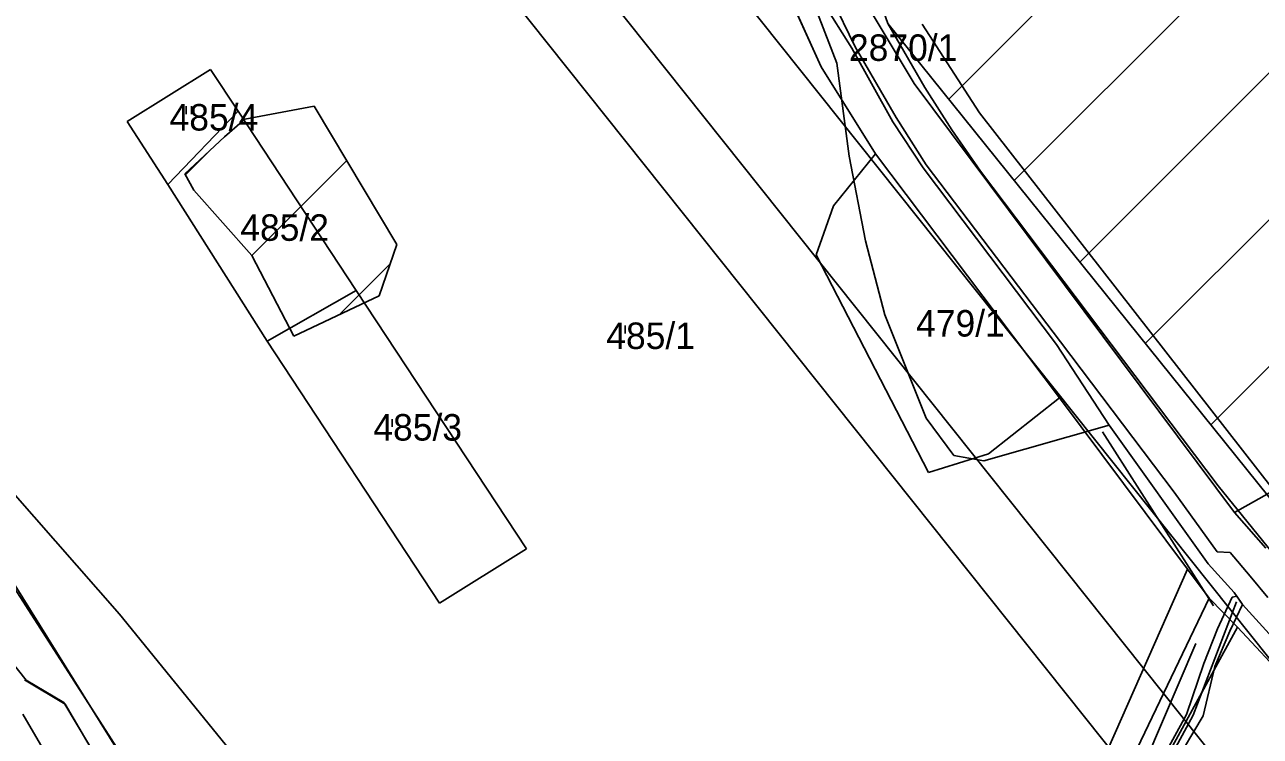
# Model space of a CAD drawing. Extents: x -564810 to -550519, y -1045831 to -1034011.
# Drawn here: x -554457.1 to -554219.2, y -1035858.3 to -1035721.3 of the extents above; entities that cross this region are included whole.
import ezdxf

# ---------------------------------------------------------------- set-up
doc = ezdxf.new("R2010")
doc.units = 0
for name, color, linetype in [('Biokoridory', 7, 'Continuous'), ('Interakční prvky', 7, 'Continuous'), ('KN stav', 7, 'Continuous'), ('Lesní porost', 7, 'Continuous'), ('Obvod KPU', 7, 'Continuous'), ('Odvodněné plochy', 7, 'Continuous'), ('Parcelní čísla', 7, 'Continuous'), ('Plynovod', 7, 'Continuous'), ('STG', 7, 'Continuous'), ('vodní toky', 7, 'Continuous'), ('Vrstva 33', 7, 'Continuous'), ('Vrstva 39', 7, 'Continuous'), ('Vrstva 4', 7, 'Continuous'), ('zamokř ploch', 7, 'Continuous')]:
    doc.layers.add(name, color=color, linetype=linetype)

msp = doc.modelspace()

# ---------------------------------------------------------------- linework, layer by layer
at = {"layer": 'Biokoridory'}
for points in [[(-554537.39, -1035746.04), (-554479.56, -1035788.42), (-554438.9, -1035834.8), (-554396.53, -1035886.91), (-554371.91, -1035929.28), (-554370.76, -1035993.98), (-554383.93, -1036106.79), (-554397.67, -1036162.33), (-554405.12, -1036209.86), (-554428.6, -1036243.51), (-554384.5, -1036328.39)], [(-554418.63, -1036320.62), (-554443.83, -1036285.12), (-554447.83, -1036247.33), (-554435.81, -1036214.69), (-554412.9, -1036187.21), (-554413.48, -1036143.11), (-554398.59, -1036095.59), (-554384.27, -1036003.97), (-554390.57, -1035936.4), (-554411.19, -1035894.6), (-554437.53, -1035863.68), (-554459.29, -1035828.75), (-554491.35, -1035800.69), (-554517.12, -1035776.07), (-554550.9, -1035757.75)]]:
    msp.add_lwpolyline(points, dxfattribs=at)
at = {"layer": 'Interakční prvky'}
msp.add_line((-554249.62, -1035799.65), (-554228.23, -1035833.15), dxfattribs=at)
msp.add_lwpolyline([(-554401.17, -1036035.23), (-554362.09, -1036026.51), (-554331.09, -1036007.77), (-554306.54, -1035979.02), (-554289.43, -1035956.72), (-554271.99, -1035924.74), (-554250.67, -1035885), (-554231.62, -1035840.41)], dxfattribs=at)
at = {"layer": 'KN stav'}
for p, q in [((-554312.36, -1035710.33), (-554303.79, -1035729.39)), ((-554303.79, -1035729.39), (-554312.36, -1035710.33)), ((-554296.78, -1035714.31), (-554285.86, -1035732.63)), ((-554421.35, -1035729.89), (-554437.42, -1035739.94)), ((-554437.42, -1035739.94), (-554421.35, -1035729.89)), ((-554416.04, -1035737.96), (-554421.35, -1035729.89)), ((-554421.35, -1035729.89), (-554416.04, -1035737.96)), ((-554303.79, -1035729.39), (-554293.31, -1035746.12)), ((-554293.31, -1035746.12), (-554303.79, -1035729.39)), ((-554285.86, -1035732.63), (-554224.16, -1035815.2)), ((-554416.04, -1035737.96), (-554429.57, -1035752.03)), ((-554393.29, -1035772.47), (-554416.04, -1035737.96)), ((-554416.04, -1035737.96), (-554393.29, -1035772.47)), ((-554437.42, -1035739.94), (-554429.57, -1035752.03)), ((-554429.57, -1035752.03), (-554437.42, -1035739.94)), ((-554293.31, -1035746.12), (-554301.41, -1035756.15)), ((-554301.41, -1035756.15), (-554293.31, -1035746.12)), ((-554257.86, -1035793.1), (-554293.31, -1035746.12)), ((-554429.57, -1035752.03), (-554410.45, -1035782.23)), ((-554410.45, -1035782.23), (-554429.57, -1035752.03)), ((-554301.41, -1035756.15), (-554304.71, -1035765.61)), ((-554304.71, -1035765.61), (-554301.41, -1035756.15)), ((-554304.71, -1035765.61), (-554283.1, -1035807.52)), ((-554283.1, -1035807.52), (-554304.71, -1035765.61)), ((-554410.45, -1035782.23), (-554393.29, -1035772.47)), ((-554360.52, -1035822.19), (-554393.29, -1035772.47)), ((-554393.29, -1035772.47), (-554360.52, -1035822.19)), ((-554159.38, -1035778.47), (-554224.16, -1035815.2)), ((-554410.45, -1035782.23), (-554377.23, -1035832.68)), ((-554377.23, -1035832.68), (-554410.45, -1035782.23)), ((-554271.54, -1035803.91), (-554257.86, -1035793.1)), ((-554257.86, -1035793.1), (-554271.54, -1035803.91)), ((-554257.86, -1035793.1), (-554233.23, -1035826.09)), ((-554233.23, -1035826.09), (-554257.86, -1035793.1)), ((-554283.1, -1035807.52), (-554271.54, -1035803.91)), ((-554271.54, -1035803.91), (-554283.1, -1035807.52)), ((-554224.16, -1035815.2), (-554218.16, -1035822.07)), ((-554377.23, -1035832.68), (-554360.52, -1035822.19)), ((-554360.52, -1035822.19), (-554377.23, -1035832.68)), ((-554233.23, -1035826.09), (-554266.98, -1035902.31)), ((-554266.98, -1035902.31), (-554233.23, -1035826.09)), ((-554233.23, -1035826.09), (-554229.04, -1035831.68)), ((-554229.04, -1035831.68), (-554259.35, -1035894.9)), ((-554223.62, -1035837.28), (-554229.04, -1035831.68)), ((-554253.13, -1035891.34), (-554223.62, -1035837.28)), ((-554223.62, -1035837.28), (-554143.85, -1035923)), ((-554449.33, -1035852.07), (-554457.19, -1035847.39)), ((-554457.19, -1035847.39), (-554449.33, -1035852.07)), ((-554428.39, -1035887.76), (-554449.33, -1035852.07)), ((-554449.33, -1035852.07), (-554428.39, -1035887.76))]:
    msp.add_line(p, q, dxfattribs=at)
at = {"layer": 'Lesní porost'}
for p, q in [((-554307.64, -1035710.79), (-554300.76, -1035728.7)), ((-554300.76, -1035728.7), (-554298.35, -1035746.57)), ((-554401.41, -1035736.98), (-554414.71, -1035739.47)), ((-554385.45, -1035763.63), (-554401.41, -1035736.98)), ((-554414.71, -1035739.47), (-554418.67, -1035742.9)), ((-554284.11, -1035748.81), (-554289.94, -1035739.98)), ((-554418.67, -1035742.9), (-554426.28, -1035749.98)), ((-554426.16, -1035750.2), (-554421.46, -1035745.5)), ((-554298.35, -1035746.57), (-554295.23, -1035762.92)), ((-554413.37, -1035765.69), (-554395.14, -1035747.46)), ((-554426.28, -1035749.98), (-554424.58, -1035753.16)), ((-554424.58, -1035753.16), (-554413.37, -1035765.69)), ((-554388.89, -1035773.5), (-554385.45, -1035763.63)), ((-554295.23, -1035762.92), (-554291.49, -1035777.15)), ((-554413.37, -1035765.69), (-554405.28, -1035781.25)), ((-554413.37, -1035765.69), (-554413.37, -1035765.69)), ((-554396.49, -1035777.09), (-554386.75, -1035767.35)), ((-554405.28, -1035781.25), (-554388.89, -1035773.5)), ((-554291.49, -1035777.15), (-554283.58, -1035797.06)), ((-554283.58, -1035797.06), (-554278.25, -1035804.2)), ((-554272.44, -1035805.27), (-554248.31, -1035798.38)), ((-554278.25, -1035804.2), (-554272.44, -1035805.27))]:
    msp.add_line(p, q, dxfattribs=at)
for points in [[(-554289.94, -1035739.98), (-554297.86, -1035725.82), (-554303.45, -1035716.95), (-554307.64, -1035710.79)], [(-554248.31, -1035798.38), (-554258.47, -1035782.83), (-554284.11, -1035748.81)]]:
    msp.add_lwpolyline(points, dxfattribs=at)
at = {"layer": 'Obvod KPU'}
for p, q in [((-554273.27, -1035738.24), (-554284.34, -1035721.21)), ((-554210.68, -1035818.61), (-554273.27, -1035738.24)), ((-554472.62, -1035827.56), (-554456.85, -1035847.5)), ((-554456.85, -1035847.5), (-554449.6, -1035851.75)), ((-554449.6, -1035851.75), (-554428.02, -1035887.99))]:
    msp.add_line(p, q, dxfattribs=at)
at = {"layer": 'Odvodněné plochy'}
for p, q in [((-554279.2, -1035735.63), (-554056.04, -1035512.47)), ((-554266.58, -1035751.3), (-554046.81, -1035531.53)), ((-554253.97, -1035766.97), (-554037.59, -1035550.59)), ((-554241.35, -1035782.64), (-554028.36, -1035569.65)), ((-554228.74, -1035798.31), (-554019.14, -1035588.71))]:
    msp.add_line(p, q, dxfattribs=at)
msp.add_lwpolyline([(-553941.08, -1036155.62), (-553804.02, -1036020.64), (-553859.83, -1035902.63), (-553900.05, -1035817.59), (-553962.27, -1035706.18), (-554082.37, -1035458.07), (-554311.27, -1035501.88), (-554358.24, -1035530.17), (-554290.96, -1035721.02)], close=True, dxfattribs=at)
at = {"layer": 'Plynovod'}
for points in [[(-554428.56, -1035578.55), (-554428.56, -1035578.55), (-554428.56, -1035578.55), (-554027.79, -1036081.22), (-553723.76, -1036467.01), (-553550.38, -1036705.78), (-553550.38, -1036705.78), (-553522.74, -1037110.43), (-553438.57, -1037242.38), (-553213.69, -1037591.73), (-553193.58, -1037703.57), (-553145.84, -1037777.72), (-553110.67, -1037838.04), (-552972.47, -1038070.52), (-552972.47, -1038070.52), (-552302.85, -1038878.56)], [(-552322.24, -1038886.46), (-552991.86, -1038078.43), (-553130.06, -1037845.94), (-553165.24, -1037785.62), (-553212.98, -1037711.48), (-553233.08, -1037599.64), (-553457.96, -1037250.28), (-553542.14, -1037118.33), (-553569.78, -1036713.69), (-553743.15, -1036474.92), (-554047.18, -1036089.12), (-554447.95, -1035586.45)], [(-552330.5, -1038899.71), (-553000.12, -1038091.67), (-553138.32, -1037859.19), (-553173.5, -1037798.87), (-553221.24, -1037724.72), (-553241.34, -1037612.88), (-553466.22, -1037263.53), (-553550.4, -1037131.58), (-553578.03, -1036726.93), (-553751.41, -1036488.16), (-554055.44, -1036102.37), (-554456.21, -1035599.7)]]:
    msp.add_lwpolyline(points, dxfattribs=at)
at = {"layer": 'STG'}
msp.add_lwpolyline([(-554188.44, -1036154.36), (-554205.89, -1036116.69), (-554227.02, -1036068.91), (-554251.82, -1036045.94), (-554283.97, -1036020.22), (-554325.31, -1035989.9), (-554340, -1035968.76), (-554364.8, -1035919.15), (-554392.36, -1035889.75), (-554408.89, -1035875.97), (-554438.29, -1035862.18), (-554461.25, -1035826.35), (-554486.05, -1035796.03), (-554510.85, -1035758.36), (-554554.94, -1035652.7), (-554579.74, -1035605.84), (-554604.55, -1035581.03), (-554667.93, -1035559.9)], dxfattribs=at)
at = {"layer": 'vodní toky'}
for p, q in [((-554224.63, -1035831.48), (-554227.43, -1035837.61)), ((-554223.72, -1035831.31), (-554224.63, -1035831.48)), ((-554225.06, -1035838.01), (-554222.61, -1035832.9)), ((-554227.43, -1035837.61), (-554230.09, -1035844.29)), ((-554227.99, -1035844.82), (-554225.06, -1035838.01)), ((-554230.09, -1035844.29), (-554233.44, -1035854.06)), ((-554230.22, -1035854.32), (-554227.99, -1035844.82)), ((-554233.44, -1035854.06), (-554240.55, -1035867.02)), ((-554238.16, -1035867.6), (-554230.22, -1035854.32))]:
    msp.add_line(p, q, dxfattribs=at)
msp.add_lwpolyline([(-554222.61, -1035832.9), (-554223.72, -1035831.31)], dxfattribs=at)
at = {"layer": 'Vrstva 33'}
msp.add_lwpolyline([(-554223.79, -1035832.41), (-554232.17, -1035854.21), (-554239.25, -1035867.4)], dxfattribs=at)
at = {"layer": 'Vrstva 39'}
for p, q in [((-554297.24, -1035725.52), (-554301.81, -1035716.13)), ((-554290.96, -1035721.02), (-554283.8, -1035733.39)), ((-554289.3, -1035739.17), (-554297.24, -1035725.52)), ((-554283.8, -1035733.39), (-554278.63, -1035741.5)), ((-554283.56, -1035748.28), (-554289.3, -1035739.17)), ((-554278.63, -1035741.5), (-554273.12, -1035749.47)), ((-554257.71, -1035782.36), (-554283.56, -1035748.28)), ((-554273.12, -1035749.47), (-554227.33, -1035810.08)), ((-554235.8, -1035811.31), (-554257.71, -1035782.36)), ((-554227.33, -1035810.08), (-554214.1, -1035826.38)), ((-554227.49, -1035822.77), (-554235.8, -1035811.31)), ((-554224.99, -1035822.91), (-554227.49, -1035822.77)), ((-554221.15, -1035827.46), (-554224.99, -1035822.91)), ((-554217.77, -1035831.53), (-554221.15, -1035827.46))]:
    msp.add_line(p, q, dxfattribs=at)
for points in [[(-553973.4, -1036146.37), (-553999.14, -1036114.51), (-554017.63, -1036088.99), (-554041.38, -1036057.15), (-554058.37, -1036032.9), (-554069.42, -1036018.66), (-554081.47, -1035999.43), (-554097.92, -1035976.65), (-554118.78, -1035949.85), (-554143.22, -1035919.7), (-554174.41, -1035884.72), (-554202.87, -1035854.66), (-554222.61, -1035832.9), (-554224.22, -1035830.59), (-554229.24, -1035825.1), (-554248.31, -1035798.38), (-554258.47, -1035782.83), (-554284.11, -1035748.81), (-554289.94, -1035739.98), (-554297.86, -1035725.82), (-554303.45, -1035716.95)], [(-554290.96, -1035721.02), (-554283.8, -1035733.39), (-554278.63, -1035741.5), (-554273.12, -1035749.47), (-554227.33, -1035810.08), (-554214.1, -1035826.38), (-554197.1, -1035845.69), (-554164.74, -1035880.04), (-554142.11, -1035905.08), (-554119.47, -1035932.42), (-554078.61, -1035985.08), (-554069.76, -1035997.24), (-554049.78, -1036025.63), (-554032.76, -1036049.63), (-554009.22, -1036081.77), (-553990.76, -1036106.5), (-553965.06, -1036139.47)]]:
    msp.add_lwpolyline(points, dxfattribs=at)
at = {"layer": 'Vrstva 4'}
msp.add_line((-554440.19, -1035883.83), (-554457.47, -1035854.01), dxfattribs=at)
at = {"layer": 'zamokř ploch'}
for p, q in [((-554426.04, -1035736.99), (-554426.04, -1035738.49)), ((-554425.04, -1035736.99), (-554425.04, -1035738.49)), ((-554342.53, -1035779.22), (-554342.53, -1035780.72)), ((-554341.53, -1035779.22), (-554341.53, -1035780.72)), ((-554387.39, -1035797.22), (-554387.39, -1035798.72)), ((-554386.39, -1035797.22), (-554386.39, -1035798.72))]:
    msp.add_line(p, q, dxfattribs=at)

# ---------------------------------------------------------------- texts
at = {"layer": 'Parcelní čísla'}
for s, p in [('2870/1', (-554298.41, -1035728.25)), ('485/4', (-554429.23, -1035741.66)), ('485/2', (-554415.61, -1035762.89)), ('479/1', (-554285.48, -1035781.32)), ('485/1', (-554345.14, -1035783.72)), ('485/3', (-554389.99, -1035801.35))]:
    msp.add_text(s, height=5.1, dxfattribs=at).set_placement(p)

doc.saveas('drawing.dxf')
